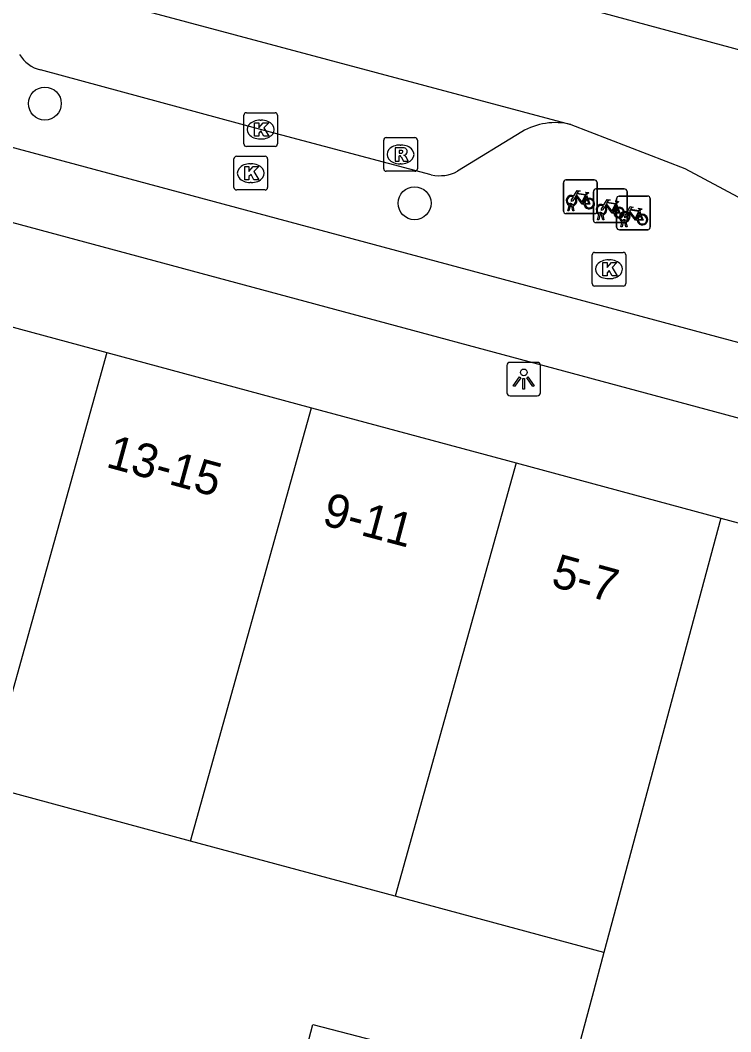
# Model space of a CAD drawing. Extents: x 160676 to 161153, y 383244 to 383713.
# Drawn here: x 160828.58 to 160849.7, y 383552.73 to 383582.77 of the extents above; entities that cross this region are included whole.
import ezdxf

# ---------------------------------------------------------------- set-up
doc = ezdxf.new("R2010")
doc.units = 0
for name, color, linetype in [('IMGEO_Boom', 7, 'Continuous'), ('IMGEO_Fietsenrek', 7, 'Continuous'), ('IMGEO_Fietspad_gesloten', 7, 'Continuous'), ('IMGEO_Kolk', 7, 'Continuous'), ('IMGEO_Lichtpunt', 7, 'Continuous'), ('IMGEO_Pand', 7, 'Continuous'), ('IMGEO_Pand_nummerreeks', 7, 'Continuous'), ('IMGEO_Parkeervlak_open', 7, 'Continuous'), ('IMGEO_Rijbaan_lokaal_gesloten', 7, 'Continuous'), ('IMGEO_Rioolput', 7, 'Continuous')]:
    doc.layers.add(name, color=color, linetype=linetype)

msp = doc.modelspace()

# ---------------------------------------------------------------- linework, layer by layer
at = {"layer": 'IMGEO_Boom'}
for centre in [(160829.311, 383580.297), (160840.301, 383577.337)]:
    msp.add_circle(centre, 0.489, dxfattribs=at)
at = {"layer": 'IMGEO_Fietsenrek'}
for p, q in [((160844.725, 383577.102), (160844.725, 383577.943)), ((160844.725, 383577.943), (160844.725, 383577.102)), ((160844.8, 383578.027), (160845.641, 383578.027)), ((160845.641, 383578.027), (160844.8, 383578.027)), ((160845.725, 383577.952), (160845.725, 383577.111)), ((160845.725, 383577.111), (160845.725, 383577.952)), ((160845.615, 383576.835), (160845.615, 383577.676)), ((160845.615, 383577.676), (160845.615, 383576.835)), ((160845.69, 383577.76), (160846.531, 383577.76)), ((160846.531, 383577.76), (160845.69, 383577.76)), ((160846.615, 383577.685), (160846.615, 383576.844)), ((160846.615, 383576.844), (160846.615, 383577.685)), ((160845.412, 383577.576), (160845.448, 383577.481)), ((160846.305, 383576.623), (160846.305, 383577.464)), ((160846.305, 383577.464), (160846.305, 383576.623)), ((160846.38, 383577.548), (160847.221, 383577.548)), ((160847.221, 383577.548), (160846.38, 383577.548)), ((160847.305, 383577.473), (160847.305, 383576.632)), ((160847.305, 383576.632), (160847.305, 383577.473)), ((160844.852, 383577.111), (160844.891, 383577.271)), ((160844.886, 383577.111), (160844.852, 383577.111)), ((160844.921, 383577.259), (160844.886, 383577.111)), ((160844.963, 383577.283), (160844.962, 383577.287)), ((160845.004, 383577.111), (160844.97, 383577.253)), ((160844.994, 383577.294), (160844.995, 383577.287)), ((160845.002, 383577.257), (160845.037, 383577.111)), ((160845.037, 383577.111), (160845.004, 383577.111)), ((160846.302, 383577.309), (160846.338, 383577.214)), ((160846.992, 383577.097), (160847.028, 383577.002)), ((160845.65, 383577.027), (160844.809, 383577.027)), ((160844.809, 383577.027), (160845.65, 383577.027)), ((160846.54, 383576.76), (160845.699, 383576.76)), ((160845.699, 383576.76), (160846.54, 383576.76)), ((160845.742, 383576.844), (160845.781, 383577.004)), ((160845.776, 383576.844), (160845.742, 383576.844)), ((160845.811, 383576.992), (160845.776, 383576.844)), ((160845.853, 383577.016), (160845.852, 383577.02)), ((160845.894, 383576.844), (160845.86, 383576.986)), ((160845.884, 383577.027), (160845.885, 383577.02)), ((160845.892, 383576.99), (160845.927, 383576.844)), ((160845.927, 383576.844), (160845.894, 383576.844)), ((160846.432, 383576.632), (160846.471, 383576.792)), ((160846.501, 383576.78), (160846.466, 383576.632)), ((160846.543, 383576.804), (160846.542, 383576.808)), ((160846.584, 383576.632), (160846.55, 383576.774)), ((160846.574, 383576.815), (160846.575, 383576.808)), ((160846.582, 383576.778), (160846.617, 383576.632)), ((160847.23, 383576.548), (160846.389, 383576.548)), ((160846.389, 383576.548), (160847.23, 383576.548)), ((160846.466, 383576.632), (160846.432, 383576.632)), ((160846.617, 383576.632), (160846.584, 383576.632))]:
    msp.add_line(p, q, dxfattribs=at)
for points in [[(160845.038, 383577.553), (160845.133, 383577.717), (160845.219, 383577.703), (160845.221, 383577.694), (160845.165, 383577.683), (160845.138, 383577.638), (160845.394, 383577.597)], [(160845.394, 383577.597), (160845.419, 383577.646), (160845.413, 383577.65), (160845.39, 383577.654), (160845.378, 383577.661), (160845.377, 383577.664), (160845.379, 383577.669), (160845.474, 383577.654), (160845.476, 383577.644), (160845.466, 383577.631), (160845.454, 383577.625), (160845.44, 383577.631), (160845.412, 383577.576)], [(160845.059, 383577.501), (160845.007, 383577.411), (160844.967, 383577.386), (160844.968, 383577.433), (160845.023, 383577.527)], [(160845.334, 383577.309), (160845.284, 383577.309), (160845.093, 383577.56), (160845.074, 383577.528)], [(160845.381, 383577.572), (160845.124, 383577.613), (160845.107, 383577.584), (160845.274, 383577.364), (160845.381, 383577.572)], [(160845.429, 383577.474), (160845.399, 383577.551), (160845.29, 383577.333), (160845.333, 383577.333)], [(160845.363, 383577.333), (160845.483, 383577.332), (160845.439, 383577.446)], [(160845.459, 383577.453), (160845.514, 383577.308), (160845.364, 383577.308)], [(160845.928, 383577.286), (160846.023, 383577.45), (160846.109, 383577.436), (160846.111, 383577.427), (160846.055, 383577.416), (160846.028, 383577.371), (160846.284, 383577.33)], [(160846.271, 383577.305), (160846.014, 383577.346), (160845.997, 383577.317), (160846.164, 383577.097), (160846.271, 383577.305)], [(160846.284, 383577.33), (160846.309, 383577.379), (160846.303, 383577.383), (160846.28, 383577.387), (160846.268, 383577.394), (160846.267, 383577.397), (160846.269, 383577.402), (160846.364, 383577.387), (160846.366, 383577.377), (160846.356, 383577.364), (160846.344, 383577.358), (160846.33, 383577.364), (160846.302, 383577.309)], [(160845.949, 383577.234), (160845.897, 383577.144), (160845.857, 383577.119), (160845.858, 383577.166), (160845.913, 383577.26)], [(160846.224, 383577.042), (160846.174, 383577.042), (160845.983, 383577.293), (160845.964, 383577.261)], [(160846.319, 383577.207), (160846.289, 383577.284), (160846.18, 383577.066), (160846.223, 383577.066)], [(160846.253, 383577.066), (160846.373, 383577.065), (160846.329, 383577.179)], [(160846.349, 383577.186), (160846.404, 383577.041), (160846.254, 383577.041)], [(160846.639, 383577.022), (160846.587, 383576.932), (160846.547, 383576.907), (160846.548, 383576.954), (160846.603, 383577.048)], [(160846.618, 383577.074), (160846.713, 383577.238), (160846.799, 383577.224), (160846.801, 383577.215), (160846.745, 383577.204), (160846.718, 383577.159), (160846.974, 383577.118)], [(160846.914, 383576.83), (160846.864, 383576.83), (160846.673, 383577.081), (160846.654, 383577.049)], [(160846.961, 383577.093), (160846.704, 383577.134), (160846.687, 383577.105), (160846.854, 383576.885), (160846.961, 383577.093)], [(160847.009, 383576.995), (160846.979, 383577.072), (160846.87, 383576.854), (160846.913, 383576.854)], [(160846.974, 383577.118), (160846.999, 383577.167), (160846.993, 383577.171), (160846.97, 383577.175), (160846.958, 383577.182), (160846.957, 383577.185), (160846.959, 383577.19), (160847.054, 383577.175), (160847.056, 383577.165), (160847.046, 383577.152), (160847.034, 383577.146), (160847.02, 383577.152), (160846.992, 383577.097)], [(160846.943, 383576.854), (160847.063, 383576.853), (160847.019, 383576.967)], [(160847.039, 383576.974), (160847.094, 383576.829), (160846.944, 383576.829)]]:
    msp.add_lwpolyline(points, dxfattribs=at)
for centre, radius, start, end in [((160844.803, 383577.949), 0.0779, 92.4484, 184.2845), ((160844.803, 383577.949), 0.0779, 92.4484, 184.2845), ((160845.647, 383577.949), 0.0779, 2.4484, 94.2845), ((160845.647, 383577.949), 0.0779, 2.4484, 94.2845), ((160845.693, 383577.682), 0.0779, 92.4484, 184.2845), ((160845.693, 383577.682), 0.0779, 92.4484, 184.2845), ((160846.537, 383577.682), 0.0779, 2.4484, 94.2845), ((160846.537, 383577.682), 0.0779, 2.4484, 94.2845), ((160844.965, 383577.412), 0.159, 62.6766, 242.1369), ((160844.965, 383577.412), 0.129, 63.3192, 238.903), ((160844.965, 383577.412), 0.129, 283.6043, 43.4302), ((160844.965, 383577.412), 0.159, 283.5766, 46.6042), ((160845.492, 383577.328), 0.159, 113.3408, 178.3217), ((160845.492, 383577.328), 0.159, 187.0065, 105.7708), ((160845.492, 383577.328), 0.129, 113.923, 177.9556), ((160845.492, 383577.328), 0.129, 188.6715, 104.5883), ((160846.383, 383577.47), 0.0779, 92.4484, 184.2845), ((160846.383, 383577.47), 0.0779, 92.4484, 184.2845), ((160847.227, 383577.47), 0.0779, 2.4484, 94.2845), ((160847.227, 383577.47), 0.0779, 2.4484, 94.2845), ((160844.803, 383577.105), 0.0779, 182.4484, 274.2845), ((160844.803, 383577.105), 0.0779, 182.4484, 274.2845), ((160844.945, 383577.283), 0.0499, 12.8025, 158.6934), ((160844.965, 383577.412), 0.159, 253.9967, 271.7867), ((160844.945, 383577.283), 0.0174, 12.8025, 163.4502), ((160844.965, 383577.412), 0.129, 253.415, 269.0204), ((160845.647, 383577.105), 0.0779, 272.4484, 4.2845), ((160845.647, 383577.105), 0.0779, 272.4484, 4.2845), ((160845.855, 383577.145), 0.159, 62.6766, 242.1369), ((160845.855, 383577.145), 0.129, 63.3192, 238.903), ((160845.835, 383577.016), 0.0499, 12.8025, 158.6934), ((160845.855, 383577.145), 0.129, 283.6043, 43.4302), ((160845.855, 383577.145), 0.159, 283.5766, 46.6042), ((160846.382, 383577.061), 0.159, 113.3408, 178.3217), ((160846.382, 383577.061), 0.159, 187.0065, 105.7708), ((160846.382, 383577.061), 0.129, 113.923, 177.9556), ((160846.382, 383577.061), 0.129, 188.6715, 104.5883), ((160846.545, 383576.933), 0.159, 62.6766, 242.1369), ((160846.545, 383576.933), 0.129, 63.3192, 238.903), ((160846.545, 383576.933), 0.159, 283.5766, 46.6042), ((160845.693, 383576.838), 0.0779, 182.4484, 274.2845), ((160845.693, 383576.838), 0.0779, 182.4484, 274.2845), ((160845.855, 383577.145), 0.159, 253.9967, 271.7867), ((160845.835, 383577.016), 0.0174, 12.8025, 163.4502), ((160845.855, 383577.145), 0.129, 253.415, 269.0204), ((160846.525, 383576.804), 0.0499, 12.8025, 158.6934), ((160846.545, 383576.933), 0.159, 253.9967, 271.7867), ((160846.525, 383576.804), 0.0174, 12.8025, 163.4502), ((160846.545, 383576.933), 0.129, 253.415, 269.0204), ((160846.537, 383576.838), 0.0779, 272.4484, 4.2845), ((160846.537, 383576.838), 0.0779, 272.4484, 4.2845), ((160846.545, 383576.933), 0.129, 283.6043, 43.4302), ((160847.072, 383576.849), 0.159, 113.3408, 178.3217), ((160847.072, 383576.849), 0.159, 187.0065, 105.7708), ((160847.072, 383576.849), 0.129, 113.923, 177.9556), ((160847.072, 383576.849), 0.129, 188.6715, 104.5883), ((160846.383, 383576.626), 0.0779, 182.4484, 274.2845), ((160846.383, 383576.626), 0.0779, 182.4484, 274.2845), ((160847.227, 383576.626), 0.0779, 272.4484, 4.2845), ((160847.227, 383576.626), 0.0779, 272.4484, 4.2845)]:
    msp.add_arc(centre, radius, start, end, dxfattribs=at)
at = {"layer": 'IMGEO_Fietspad_gesloten'}
for points in [[(160904.417, 383556.04), (160869.912, 383565.633), (160851.652, 383570.489), (160741.54, 383600.127)], [(160753.356, 383599.164), (160754.374, 383598.874), (160872.54, 383567.128), (160873.601, 383566.834)]]:
    msp.add_lwpolyline(points, dxfattribs=at)
at = {"layer": 'IMGEO_Kolk'}
for p, q in [((160835.226, 383579.098), (160835.226, 383579.95)), ((160835.301, 383580.024), (160836.153, 383580.024)), ((160835.714, 383579.804), (160835.739, 383579.804)), ((160836.227, 383579.95), (160836.227, 383579.098)), ((160835.737, 383579.244), (160835.712, 383579.244)), ((160836.153, 383579.024), (160835.301, 383579.024)), ((160834.931, 383577.804), (160834.931, 383578.656)), ((160835.006, 383578.73), (160835.858, 383578.73)), ((160835.932, 383578.656), (160835.932, 383577.804)), ((160835.419, 383578.51), (160835.444, 383578.51)), ((160835.442, 383577.95), (160835.417, 383577.95)), ((160835.858, 383577.73), (160835.006, 383577.73)), ((160845.652, 383575.876), (160846.504, 383575.876)), ((160845.577, 383574.95), (160845.577, 383575.802)), ((160846.065, 383575.656), (160846.09, 383575.656)), ((160846.578, 383575.802), (160846.578, 383574.95)), ((160846.088, 383575.096), (160846.063, 383575.096)), ((160846.504, 383574.876), (160845.652, 383574.876))]:
    msp.add_line(p, q, dxfattribs=at)
for points in [[(160835.226, 383579.098), (160835.226, 383579.95)], [(160835.301, 383580.024), (160836.153, 383580.024)], [(160836.227, 383579.95), (160836.227, 383579.098)], [(160835.547, 383579.724), (160835.67, 383579.724), (160835.67, 383579.573), (160835.8, 383579.724), (160835.964, 383579.724), (160835.818, 383579.573), (160835.971, 383579.324), (160835.819, 383579.324), (160835.734, 383579.488), (160835.67, 383579.421), (160835.67, 383579.324), (160835.547, 383579.324), (160835.547, 383579.724)], [(160836.153, 383579.024), (160835.301, 383579.024)], [(160834.931, 383577.804), (160834.931, 383578.656)], [(160835.006, 383578.73), (160835.858, 383578.73)], [(160835.932, 383578.656), (160835.932, 383577.804)], [(160835.252, 383578.43), (160835.375, 383578.43), (160835.375, 383578.279), (160835.505, 383578.43), (160835.669, 383578.43), (160835.523, 383578.279), (160835.676, 383578.03), (160835.524, 383578.03), (160835.439, 383578.194), (160835.375, 383578.127), (160835.375, 383578.03), (160835.252, 383578.03), (160835.252, 383578.43)], [(160835.858, 383577.73), (160835.006, 383577.73)], [(160845.652, 383575.876), (160846.504, 383575.876)], [(160845.577, 383574.95), (160845.577, 383575.802)], [(160845.898, 383575.576), (160846.021, 383575.576), (160846.021, 383575.425), (160846.151, 383575.576), (160846.315, 383575.576), (160846.169, 383575.425), (160846.322, 383575.176), (160846.17, 383575.176), (160846.085, 383575.34), (160846.021, 383575.273), (160846.021, 383575.176), (160845.898, 383575.176), (160845.898, 383575.576)], [(160846.578, 383575.802), (160846.578, 383574.95)], [(160846.504, 383574.876), (160845.652, 383574.876)]]:
    msp.add_lwpolyline(points, dxfattribs=at)
for centre, start, end in [((160835.303, 383579.948), 91.552, 178.448), ((160835.303, 383579.948), 91.552, 178.448), ((160836.151, 383579.948), 1.552, 88.448), ((160836.151, 383579.948), 1.552, 88.448), ((160835.303, 383579.1), 181.552, 268.448), ((160835.303, 383579.1), 181.552, 268.448), ((160836.151, 383579.1), 271.552, 358.448), ((160836.151, 383579.1), 271.552, 358.448), ((160835.008, 383578.654), 91.552, 178.448), ((160835.008, 383578.654), 91.552, 178.448), ((160835.856, 383578.654), 1.552, 88.448), ((160835.856, 383578.654), 1.552, 88.448), ((160835.008, 383577.806), 181.552, 268.448), ((160835.008, 383577.806), 181.552, 268.448), ((160835.856, 383577.806), 271.552, 358.448), ((160835.856, 383577.806), 271.552, 358.448), ((160845.654, 383575.8), 91.552, 178.448), ((160845.654, 383575.8), 91.552, 178.448), ((160846.502, 383575.8), 1.552, 88.448), ((160846.502, 383575.8), 1.552, 88.448), ((160845.654, 383574.952), 181.552, 268.448), ((160845.654, 383574.952), 181.552, 268.448), ((160846.502, 383574.952), 271.552, 358.448), ((160846.502, 383574.952), 271.552, 358.448)]:
    msp.add_arc(centre, 0.0765, start, end, dxfattribs=at)
for centre, major_axis, ratio, start_param, end_param in [((160835.713, 383579.524), (-0.387, 0.002), 0.722429, 4.712389, 7.853982), ((160835.738, 383579.524), (-0.39, 0.002), 0.717154, 1.570796, 4.712389), ((160835.418, 383578.23), (-0.387, 0.002), 0.722429, 4.712389, 7.853982), ((160835.443, 383578.23), (-0.39, 0.002), 0.717154, 1.570796, 4.712389), ((160846.064, 383575.376), (-0.387, 0.002), 0.722429, 4.712389, 7.853982), ((160846.089, 383575.376), (-0.39, 0.002), 0.717154, 1.570796, 4.712389)]:
    msp.add_ellipse(centre, major_axis=major_axis, ratio=ratio, start_param=start_param, end_param=end_param, dxfattribs=at)
at = {"layer": 'IMGEO_Lichtpunt'}
for p, q in [((160843.949, 383572.611), (160843.141, 383572.611)), ((160843.949, 383572.611), (160843.141, 383572.611)), ((160843.047, 383572.516), (160843.047, 383571.709)), ((160843.047, 383572.516), (160843.047, 383571.709)), ((160844.043, 383571.709), (160844.043, 383572.516)), ((160844.043, 383571.709), (160844.043, 383572.516)), ((160843.141, 383571.615), (160843.949, 383571.615)), ((160843.141, 383571.615), (160843.949, 383571.615))]:
    msp.add_line(p, q, dxfattribs=at)
for points in [[(160843.421, 383572.18), (160843.46, 383572.152), (160843.272, 383571.89), (160843.234, 383571.917), (160843.421, 383572.18)], [(160843.523, 383572.132), (160843.57, 383572.132), (160843.57, 383571.81), (160843.523, 383571.81), (160843.523, 383572.132)], [(160843.633, 383572.152), (160843.671, 383572.179), (160843.858, 383571.917), (160843.819, 383571.889), (160843.633, 383572.152)]]:
    msp.add_lwpolyline(points, dxfattribs=at)
msp.add_circle((160843.546, 383572.314), 0.0994, dxfattribs=at)
for centre, start, end in [((160843.141, 383572.516), 90, 180), ((160843.141, 383572.516), 90, 180), ((160843.949, 383572.516), 0, 90), ((160843.949, 383572.516), 0, 90), ((160843.141, 383571.709), 180, 270), ((160843.141, 383571.709), 180, 270), ((160843.949, 383571.709), 270, 0), ((160843.949, 383571.709), 270, 360)]:
    msp.add_arc(centre, 0.0946, start, end, dxfattribs=at)
at = {"layer": 'IMGEO_Pand'}
for points in [[(160825.065, 383574.542), (160831.149, 383572.903)], [(160831.149, 383572.903), (160827.553, 383560.031)], [(160831.149, 383572.903), (160837.232, 383571.265)], [(160833.637, 383558.393), (160837.232, 383571.265)], [(160837.232, 383571.265), (160843.316, 383569.626)], [(160843.316, 383569.626), (160839.72, 383556.755)], [(160843.316, 383569.626), (160849.404, 383567.986)], [(160849.404, 383567.986), (160845.929, 383555.083)], [(160849.404, 383567.986), (160857.461, 383565.816)], [(160833.637, 383558.393), (160827.553, 383560.031)], [(160839.72, 383556.755), (160833.637, 383558.393)], [(160845.929, 383555.083), (160839.72, 383556.755)], [(160845.929, 383555.083), (160845.578, 383553.78), (160844.825, 383550.984)], [(160835.773, 383546.777), (160835.675, 383546.802), (160837.272, 383552.948), (160839.91, 383552.262), (160844.825, 383550.984)]]:
    msp.add_lwpolyline(points, dxfattribs=at)
at = {"layer": 'IMGEO_Parkeervlak_open'}
for points in [[(160840.798, 383578.179), (160835.724, 383579.525), (160829.183, 383581.295)], [(160843.487, 383579.458), (160841.581, 383578.286)]]:
    msp.add_lwpolyline(points, dxfattribs=at)
for centre, radius, start, end in [((160829.416, 383582.254), 0.987, 210.1675, 256.3296), ((160844.481, 383577.775), 1.955, 76.1555, 120.5763), ((160841.039, 383579.333), 1.179, 258.2062, 297.3568)]:
    msp.add_arc(centre, radius, start, end, dxfattribs=at)
at = {"layer": 'IMGEO_Rijbaan_lokaal_gesloten'}
for points in [[(160913.282, 383564.496), (160869.874, 383576.512), (160797.171, 383596.125)], [(160826.28, 383584.667), (160844.949, 383579.673)], [(160844.949, 383579.673), (160848.337, 383578.365), (160853.656, 383575.522)]]:
    msp.add_lwpolyline(points, dxfattribs=at)
at = {"layer": 'IMGEO_Rioolput'}
for p, q in [((160839.383, 383578.36), (160839.383, 383579.212)), ((160839.458, 383579.286), (160840.31, 383579.286)), ((160840.384, 383579.212), (160840.384, 383578.36)), ((160839.871, 383579.066), (160839.896, 383579.066)), ((160840.31, 383578.286), (160839.458, 383578.286)), ((160839.894, 383578.506), (160839.869, 383578.506))]:
    msp.add_line(p, q, dxfattribs=at)
for points in [[(160839.383, 383578.36), (160839.383, 383579.212)], [(160839.458, 383579.286), (160840.31, 383579.286)], [(160840.384, 383579.212), (160840.384, 383578.36)], [(160839.972, 383578.984), (160839.72, 383578.986), (160839.72, 383578.586)], [(160839.898, 383578.905), (160839.844, 383578.905), (160839.844, 383578.824)], [(160839.72, 383578.586), (160839.844, 383578.586), (160839.844, 383578.748), (160839.855, 383578.748)], [(160839.844, 383578.824), (160839.896, 383578.824)], [(160839.902, 383578.719), (160839.973, 383578.586), (160840.113, 383578.586), (160840.048, 383578.712)], [(160840.31, 383578.286), (160839.458, 383578.286)]]:
    msp.add_lwpolyline(points, dxfattribs=at)
for centre, radius, start, end in [((160839.46, 383579.21), 0.0765, 91.552, 178.448), ((160839.46, 383579.21), 0.0765, 91.552, 178.448), ((160840.308, 383579.21), 0.0765, 1.552, 88.448), ((160840.308, 383579.21), 0.0765, 1.552, 88.448), ((160839.904, 383578.809), 0.0964, 77.0061, 93.1865), ((160839.918, 383578.866), 0.0378, 276.6634, 79.6772), ((160839.971, 383578.874), 0.109, 350.3612, 89.416), ((160839.969, 383578.874), 0.112, 277.5842, 350.9817), ((160839.854, 383578.695), 0.0533, 26.0293, 88.6989), ((160839.88, 383579.013), 0.19, 274.7715, 282.9687), ((160839.953, 383578.659), 0.108, 29.5134, 73.7905), ((160839.46, 383578.362), 0.0765, 181.552, 268.448), ((160839.46, 383578.362), 0.0765, 181.552, 268.448), ((160840.308, 383578.362), 0.0765, 271.552, 358.448), ((160840.308, 383578.362), 0.0765, 271.552, 358.448)]:
    msp.add_arc(centre, radius, start, end, dxfattribs=at)
for centre, major_axis, ratio, start_param, end_param in [((160839.87, 383578.786), (-0.387, 0.002), 0.722429, 4.712389, 7.853982), ((160839.895, 383578.786), (-0.39, 0.002), 0.717154, 1.570796, 4.712389)]:
    msp.add_ellipse(centre, major_axis=major_axis, ratio=ratio, start_param=start_param, end_param=end_param, dxfattribs=at)

# ---------------------------------------------------------------- texts
at = {"layer": 'IMGEO_Pand_nummerreeks'}
for s, rotation, p in [('13-15', 344.7242, (160831.095, 383569.512)), ('9-11', 345.0686, (160837.515, 383567.795)), ('5-7', 344.6445, (160844.321, 383565.972))]:
    msp.add_text(s, height=1, rotation=rotation, dxfattribs=at).set_placement(p)

doc.saveas('drawing.dxf')
